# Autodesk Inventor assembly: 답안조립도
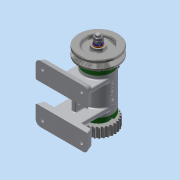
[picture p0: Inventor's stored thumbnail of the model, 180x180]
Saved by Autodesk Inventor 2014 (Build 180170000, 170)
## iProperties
Created: 2016-07
Part Number: 답안조립도
Document SubType Name: Assembly
Designer: 406-003
Author: 406-003
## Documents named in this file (16)
- C:\Users\406-003\Desktop\460707V1018\답안조립도.iam
- C:\Users\406-003\Desktop\460707V1018\V벨트풀리.ipt
- C:\Users\406-003\Desktop\460707V1018\너트 M 8.ipt
- C:\Users\406-003\Desktop\460707V1018\니플 M 6 x 0.75.ipt
- C:\Users\406-003\Desktop\460707V1018\베어링 15 x 32 x 9.ipt
- C:\Users\406-003\Desktop\460707V1018\본체.ipt
- C:\Users\406-003\Desktop\460707V1018\볼트 M 6 x 8.ipt
- C:\Users\406-003\Desktop\460707V1018\볼트 M4 x 12.ipt
- C:\Users\406-003\Desktop\460707V1018\스퍼기어.ipt
- C:\Users\406-003\Desktop\460707V1018\스프링와셔 8.ipt
- C:\Users\406-003\Desktop\460707V1018\오일 실 15 25 7.ipt
- C:\Users\406-003\Desktop\460707V1018\와셔 6x11.5.ipt
- C:\Users\406-003\Desktop\460707V1018\와셔 8x17.ipt
- C:\Users\406-003\Desktop\460707V1018\축.ipt
- C:\Users\406-003\Desktop\460707V1018\커버.ipt
- C:\Users\406-003\Desktop\460707V1018\키 3 x 3 x 12.ipt
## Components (11 placed, 3 different names)
1. V벨트풀리:1
2. KS B 2023 6002 - 15 x 32 x 9:1
3. KS B 2023 6002 - 15 x 32 x 9:2
4. ISO 4762 M4 x 12:1
5. ISO 4762 M4 x 12:2
6. ISO 4762 M4 x 12:3
7. ISO 4762 M4 x 12:4
8. ISO 4762 M4 x 12:5
9. ISO 4762 M4 x 12:6
10. ISO 4762 M4 x 12:7
11. ISO 4762 M4 x 12:8
## Named parameters: d9_d8 = 0, d26_d23 = 0, d27_d24 = 0, d28_d25 = 0
